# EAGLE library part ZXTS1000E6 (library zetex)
PNP TRANSISTOR with SHOTTKY
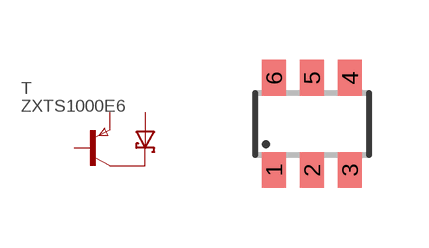
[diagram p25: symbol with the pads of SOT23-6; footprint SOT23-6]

Designator prefix T

## ZXTS1000E6 (MPN: ZXT13N50DE6; OC_FARNELL: 1471192; OC_NEWARK: 98K4165)  [SOT23-6]
1  E  pas
2  B  pas
3  A  pas
4  K  pas
5  C  pas
6  C1  pas

## Footprint SOT23-6 (pad centres in mm)
Small Outline Transistor 6 lead
smd 0.6 x 0.9: 1 -0.95,-1.15; 2 0,-1.15; 3 0.95,-1.15; 4 0.95,1.15; 5 0,1.15; 6 -0.95,1.15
